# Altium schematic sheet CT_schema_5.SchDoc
size 295 x 165 mm
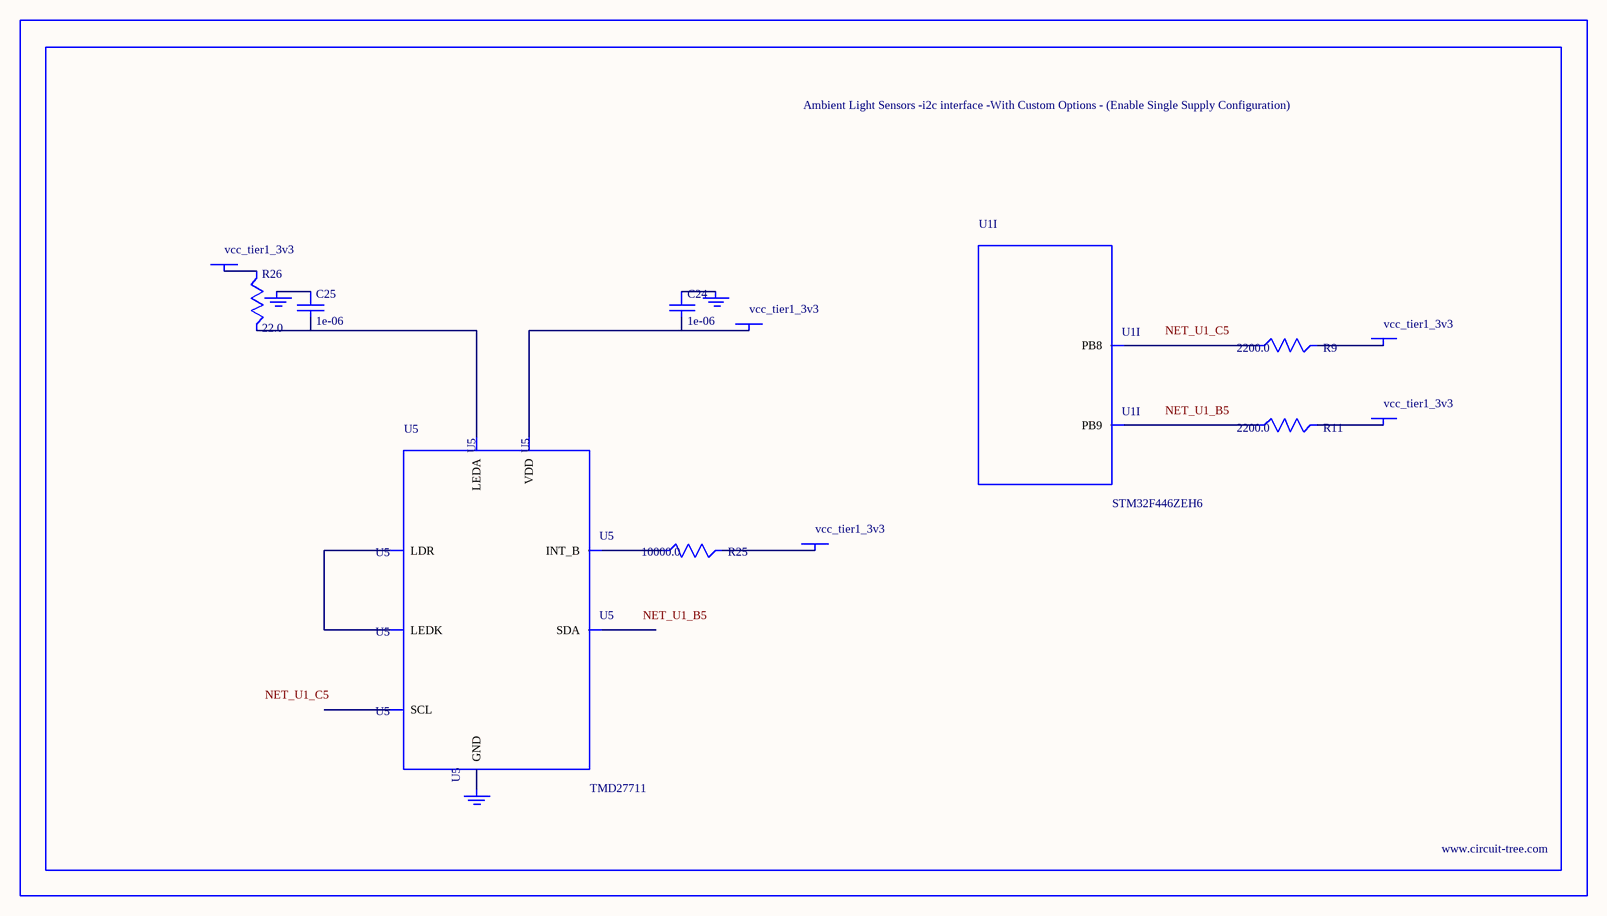
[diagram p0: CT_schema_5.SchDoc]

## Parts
BORDER4  (no value)
C24  1e-06  [C0603]
C25  1e-06  [C0603]
GND_INSTANCE_4_0  (no value)
GND_INSTANCE_4_1  (no value)
GND_INSTANCE_4_2  (no value)
POWER_INSTANCE_4_0  vcc_tier1_3v3
POWER_INSTANCE_4_1  vcc_tier1_3v3
POWER_INSTANCE_4_2  vcc_tier1_3v3
POWER_INSTANCE_4_3  vcc_tier1_3v3
POWER_INSTANCE_4_4  vcc_tier1_3v3
R9  2200.0  [R0603]
R11  2200.0  [R0603]
R25  10000.0  [R0603]
R26  22.0  [R0603]
U1  STM32F446ZEH6  [UFBGA144]  (part I of 10)
U5  TMD27711  [SMD-8]

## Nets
NetC24_1: C24.1 GND_INSTANCE_4_0.0(GND)
NetC24_2: C24.2 POWER_INSTANCE_4_0.0(PWR) U5.1(VDD)
NetC25_1: C25.1 GND_INSTANCE_4_1.0(GND)
NetC25_2: C25.2 R26.2 U5.4(LEDA)
NetGND_INSTANCE_4_2_0: GND_INSTANCE_4_2.0(GND) U5.3(GND)
NetPOWER_INSTANCE_4_1_0: POWER_INSTANCE_4_1.0(PWR) R26.1
NetPOWER_INSTANCE_4_2_0: POWER_INSTANCE_4_2.0(PWR) R25.2
NetPOWER_INSTANCE_4_3_0: POWER_INSTANCE_4_3.0(PWR) R9.2
NetPOWER_INSTANCE_4_4_0: POWER_INSTANCE_4_4.0(PWR) R11.2
NetR9_1: R9.1 U1.C5(PB8)
NetR11_1: R11.1 U1.B5(PB9)
NetR25_1: R25.1 U5.7(INT_B)
NetU5_5: U5.5(LEDK) U5.6(LDR)

Not connected (* = marked no-connect by the designer): U5 2(SCL) 8(SDA)

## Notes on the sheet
- Labels drawn without touching a wire or pin: NET_U1_B5, NET_U1_C5

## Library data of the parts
BORDER4 = BORDER_PAGE4
C24 C25 = C0603C105K3RACTU
GND_INSTANCE_4_0-GND_INSTANCE_4_2 = GND
POWER_INSTANCE_4_0-POWER_INSTANCE_4_4 = PWR
R9 R11 = RC0603JR-072K2L
R25 = RC0603JR-0710KL
R26 = RC0603JR-0722RL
